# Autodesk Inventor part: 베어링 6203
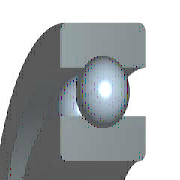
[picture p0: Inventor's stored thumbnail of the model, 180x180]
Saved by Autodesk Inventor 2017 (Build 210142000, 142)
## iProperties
IsCustomPart: 0
Created: 2018-09
Part Number: 베어링 6203
Material: 스테인리스강
Description: 깊은 그루브 볼 베어링
Document SubType Name: Modeling
Standard: KS B 2023
Standards Organization: KS
Language: ko-KR
Size Designation: 6203 - 17 x 40 x 12
Categories: <MemberInstance><Categories><Category DisplayName="샤프트 부품" InternalName="7f7aeb1f-a693-4053-b835-cee3144e0d98" Mnemonic="SHFT"><Category DisplayName="베어링" Inter
Density: 8.08 g/cm^3
Mass: 66.7997 g
Surface Area: 64.3582 cm^2
Volume: 8.26729 cm^3
Appearance: 보라색
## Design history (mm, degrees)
sketch "스케치" dims "d0" = 5.98 (= -0.26 x WD + 0.26 x BD)
  geometry: L1 (3.01, 14.25)-(8.99, 14.25); L2 (6, 14.25)-(6, 11.26); L3 (6, 14.25)-(6, 17.24); L4 (3.778, 12.249)-(0, 12.249); L5 (0, 8.5)-(12, 8.5); L6 (3.778, 16.251)-(0, 16.251); L7 (0, 20)-(12, 20); L8 (12, 8.5)-(12, 12.249); L9 (8.222, 12.249)-(12, 12.249); L10 (8.222, 16.251)-(12, 16.251); L11 (12, 20)-(12, 16.251); L12 (-1.4, 0)-(8.4, 0) reference; L13 (0, -0.3)-(0, 5.3) reference
  constraints: 22 end point, 4 point on line, 2 collinear, 2 perpendicular, 2 symmetric about line, 1 midpoint, 1 parallel, 14 other
  dimensions: "d9" = 17 diameter of L5 L12 (= WD); "d11" = 40 diameter of L7 L12 (= BD); "d12" = 12 distance between parallel lines of L8 L13 (= KB); "d13" = 24.498 diameter of L9 L12 (= 0.326 x BD + 0.674 x WD)
revolve "본체" stored, may be unused: angle "d6" = 90 deg
revolve "볼" stored, may be unused: angle "d7" = 90 deg
pattern_circular "IDS_ARRAYBALL[SIMPL:T]" dims angle "d3" = 360 deg
body "Solid1"
fillet "모깎기1" dims "d1" = 0.6 (= KRS)
other parameters: "WD" = 17 [user parameter; used in 5 equation terms], "BD" = 40 [user parameter; used in 5 equation terms], "KB" = 12 [user parameter; used in 1 equation term], "KRS" = 0.6 [user parameter; used in 1 equation term], "d4" = 0, "d5" = 0, "d8" = 0, "d14" = 0, "d15" = 0, "BBA" = 0 [user parameter], "BC0" = 4750000 [user parameter], "BC" = 9560000 [user parameter], "WR" = 8.5 (= 0.5 x WD) [user parameter]
